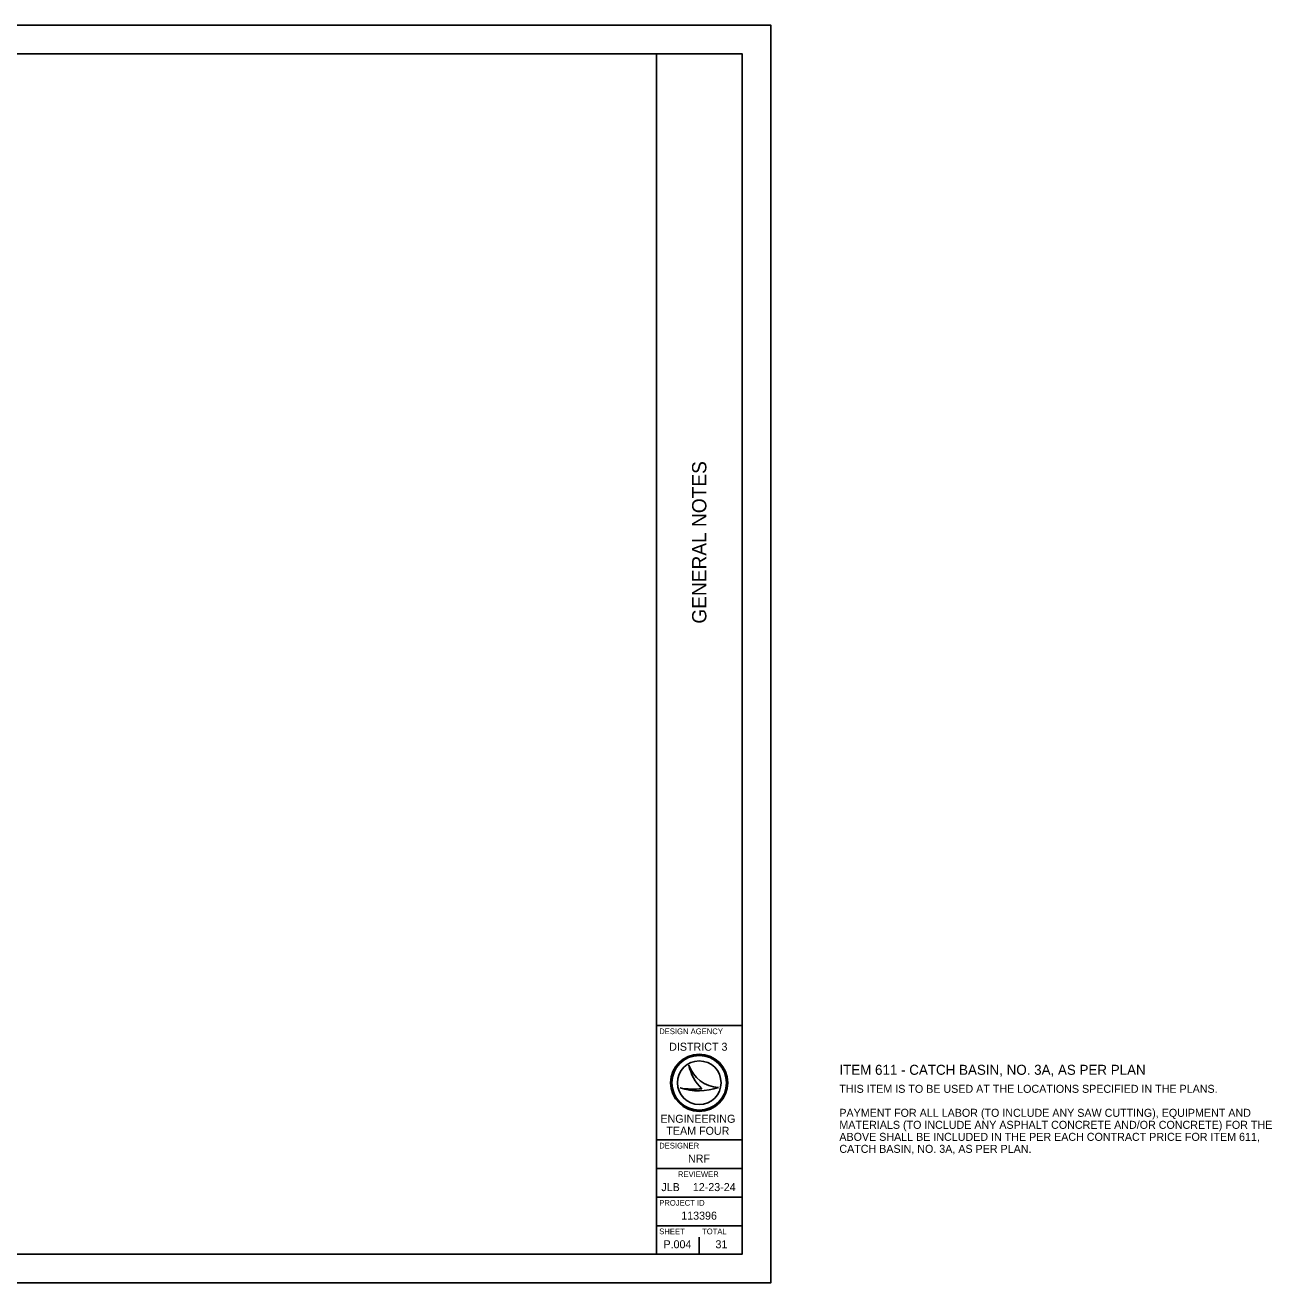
# Model space of a CAD drawing. Extents: x -9.7 to 42.8, y 0 to 45.4.
# Drawn here: x 20.96 to 42.77, y 0 to 22 of the extents above; entities that cross this region are included whole.
import ezdxf

# ---------------------------------------------------------------- set-up
doc = ezdxf.new("R2010")
doc.units = 0
for name, color, linetype in [('SH_Border', 7, 'Continuous'), ('SH_Cut_Line', 7, 'Continuous'), ('SH_Data', 7, 'Continuous'), ('TX_P_1', 7, 'Continuous')]:
    doc.layers.add(name, color=color, linetype=linetype)

msp = doc.modelspace()

# ---------------------------------------------------------------- linework, layer by layer
at = {"layer": 'SH_Border'}
for p, q in [((32, 0.5), (32, 21.5)), ((32, 4.5), (33.5, 4.5)), ((32, 2.5), (33.5, 2.5)), ((32, 2), (33.5, 2)), ((32, 1.5), (33.5, 1.5)), ((32, 1), (33.5, 1))]:
    msp.add_line(p, q, dxfattribs=at)
msp.add_lwpolyline([(1.5, 21.5), (33.5, 21.5), (33.5, 0.5), (1.5, 0.5)], close=True, dxfattribs=at)
at = {"layer": 'SH_Cut_Line'}
msp.add_lwpolyline([(0, 0), (34, 0), (34, 22), (0, 22)], close=True, dxfattribs=at)
at = {"layer": 'SH_Data'}
for p, q in [((32.567, 3.81), (32.567, 3.81)), ((32.417, 3.41), (32.417, 3.41)), ((32.75, 3.5), (32.75, 3.5)), ((33.087, 3.419), (33.087, 3.419)), ((32.375, 0.675), (32.375, 0.675)), ((32.75, 0.5), (32.75, 0.8))]:
    msp.add_line(p, q, dxfattribs=at)
for radius in [0.5, 0.477, 0.477, 0.382]:
    msp.add_circle((32.75, 3.5), radius, dxfattribs=at)
for centre, radius, start, end in [((33.116, 3.998), 0.58, 198.9257, 198.9319), ((33.347, 3.97), 0.796, 191.6379, 191.6421), ((33.116, 3.998), 0.58, 198.9319, 267.1657), ((33.347, 3.97), 0.796, 191.6421, 226.0947), ((32.739, 4.37), 1.013, 251.4576, 290.0832), ((32.648, 4.654), 1.266, 259.4964, 259.4995), ((32.739, 4.37), 1.013, 251.4527, 251.4576), ((32.648, 4.654), 1.266, 259.4995, 276.6672)]:
    msp.add_arc(centre, radius, start, end, dxfattribs=at)

# ---------------------------------------------------------------- texts
msp.add_text('GENERAL NOTES', height=0.25, rotation=90, dxfattribs=at).set_placement((32.875, 11.531))
for s, height, p in [('DESIGN AGENCY', 0.1, (32.05, 4.35)), ('DISTRICT 3', 0.14, (32.224, 4.06)), ('ENGINEERING', 0.14, (32.071, 2.8)), ('TEAM FOUR', 0.14, (32.175, 2.59)), ('DESIGNER', 0.1, (32.05, 2.35)), ('NRF', 0.14, (32.553, 2.105)), ('REVIEWER', 0.1, (32.378, 1.85)), ('JLB', 0.14, (32.087, 1.605)), ('12-23-24', 0.14, (32.638, 1.605)), ('PROJECT ID', 0.1, (32.05, 1.35)), ('113396', 0.14, (32.435, 1.105)), ('SHEET', 0.1, (32.05, 0.85)), ('TOTAL', 0.1, (32.8, 0.85)), ('P.004', 0.14, (32.124, 0.605)), ('31', 0.14, (33.034, 0.605))]:
    msp.add_text(s, height=height, dxfattribs=at).set_placement(p)
at = {"layer": 'TX_P_1'}
for s, height, p in [('ITEM 611 - CATCH BASIN, NO. 3A, AS PER PLAN', 0.175, (35.201, 3.639)), ('THIS ITEM IS TO BE USED AT THE LOCATIONS SPECIFIED IN THE PLANS. ', 0.14, (35.201, 3.324)), ('PAYMENT FOR ALL LABOR (TO INCLUDE ANY SAW CUTTING), EQUIPMENT AND ', 0.14, (35.201, 2.904)), ('MATERIALS (TO INCLUDE ANY ASPHALT CONCRETE AND/OR CONCRETE) FOR THE ', 0.14, (35.201, 2.694)), ('ABOVE SHALL BE INCLUDED IN THE PER EACH CONTRACT PRICE FOR ITEM 611, ', 0.14, (35.201, 2.484)), ('CATCH BASIN, NO. 3A, AS PER PLAN. ', 0.14, (35.201, 2.274))]:
    msp.add_text(s, height=height, dxfattribs=at).set_placement(p)

doc.saveas('drawing.dxf')
